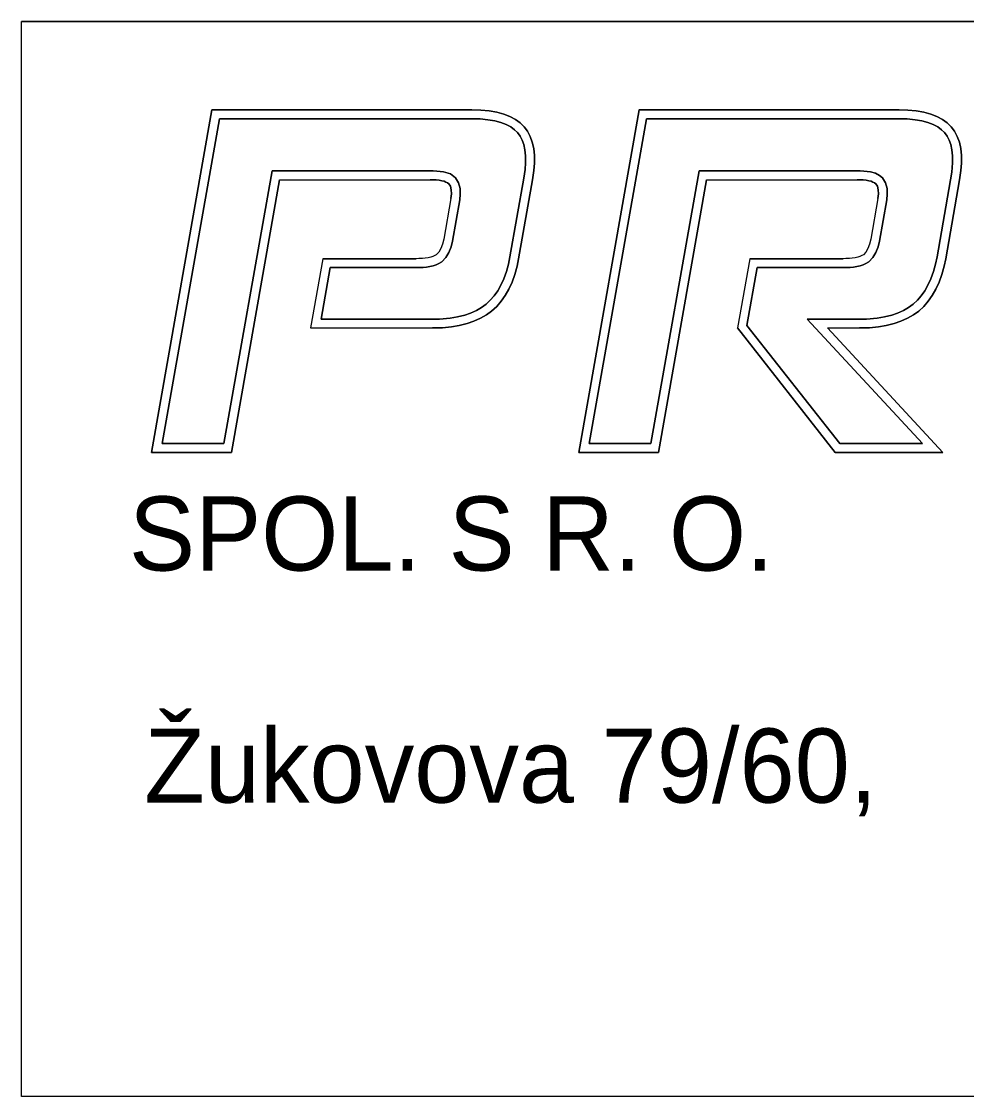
# Model space of a CAD drawing. Extents: x 362 to 677, y 239 to 384.
# Drawn here: x 645.31 to 657.42, y 260.9 to 274.68 of the extents above; entities that cross this region are included whole.
import ezdxf

# ---------------------------------------------------------------- set-up
doc = ezdxf.new("R2010")
doc.units = 0
doc.layers.add('000_rozpiska', color=7, linetype='Continuous')

msp = doc.modelspace()

# ---------------------------------------------------------------- linework, layer by layer
at = {"layer": '000_rozpiska'}
for p, q in [((672.386, 274.68), (645.311, 274.68)), ((645.311, 260.904), (645.311, 274.68)), ((646.979, 269.157), (647.752, 273.548)), ((647.751, 273.548), (651.083, 273.548)), ((652.45, 269.157), (653.223, 273.548)), ((653.222, 273.548), (656.554, 273.548)), ((648.617, 272.653), (648.001, 269.157)), ((648.617, 272.653), (650.546, 272.653)), ((651.86, 272.653), (651.681, 271.64)), ((654.088, 272.653), (653.472, 269.157)), ((654.088, 272.653), (656.017, 272.653)), ((657.331, 272.653), (657.152, 271.64)), ((650.812, 272.41), (650.721, 271.89)), ((656.283, 272.41), (656.192, 271.89)), ((649.171, 271.64), (649.014, 270.753)), ((649.171, 271.64), (650.367, 271.64)), ((654.642, 271.64), (654.485, 270.753)), ((654.642, 271.64), (655.838, 271.64)), ((649.014, 270.753), (650.579, 270.753)), ((655.738, 269.157), (654.485, 270.753)), ((655.639, 270.753), (656.05, 270.753)), ((657.114, 269.157), (655.639, 270.753)), ((648.001, 269.157), (646.979, 269.157)), ((653.472, 269.157), (652.45, 269.157)), ((657.114, 269.157), (655.738, 269.157)), ((673.621, 260.904), (645.311, 260.904))]:
    msp.add_line(p, q, dxfattribs=at)
for points in [[(645.311, 260.904), (645.311, 274.68), (672.386, 274.68)], [(651.49, 273.494), (651.401, 273.518), (651.303, 273.535), (651.196, 273.545), (651.083, 273.548), (647.752, 273.548), (646.979, 269.157), (648.001, 269.157), (648.617, 272.653), (650.546, 272.653), (650.581, 272.652), (650.622, 272.65), (650.662, 272.646), (650.695, 272.64), (650.725, 272.633), (650.749, 272.623), (650.77, 272.612), (650.786, 272.599), (650.806, 272.568), (650.818, 272.525), (650.819, 272.47), (650.812, 272.41), (650.721, 271.89), (650.706, 271.827), (650.684, 271.77), (650.658, 271.725), (650.626, 271.692), (650.606, 271.68), (650.583, 271.669), (650.554, 271.66), (650.522, 271.652), (650.485, 271.647), (650.447, 271.643), (650.402, 271.641), (650.367, 271.64), (649.171, 271.64), (649.014, 270.753), (650.579, 270.753), (650.706, 270.756), (650.819, 270.767), (650.92, 270.783), (651.022, 270.809), (651.107, 270.838), (651.193, 270.877), (651.267, 270.92), (651.335, 270.97), (651.4, 271.028), (651.457, 271.096), (651.509, 271.169), (651.556, 271.251), (651.597, 271.34), (651.632, 271.44), (651.661, 271.543), (651.681, 271.64), (651.86, 272.653), (651.877, 272.772), (651.884, 272.864), (651.882, 272.964), (651.874, 273.052), (651.856, 273.135), (651.83, 273.206), (651.796, 273.273), (651.752, 273.331), (651.7, 273.382), (651.639, 273.426), (651.568, 273.463), (651.49, 273.494)], [(651.083, 273.548), (651.196, 273.545), (651.303, 273.535), (651.401, 273.518), (651.49, 273.494), (651.568, 273.463), (651.639, 273.426), (651.7, 273.382), (651.752, 273.331), (651.796, 273.273), (651.83, 273.206), (651.856, 273.135), (651.874, 273.052), (651.882, 272.964), (651.884, 272.864), (651.877, 272.772), (651.86, 272.653)], [(657.348, 272.772), (657.355, 272.864), (657.353, 272.964), (657.345, 273.052), (657.327, 273.135), (657.301, 273.206), (657.267, 273.273), (657.223, 273.331), (657.171, 273.382), (657.11, 273.426), (657.039, 273.463), (656.961, 273.494), (656.872, 273.518), (656.774, 273.535), (656.667, 273.545), (656.554, 273.548), (653.223, 273.548), (652.45, 269.157), (653.472, 269.157), (654.088, 272.653), (656.017, 272.653), (656.052, 272.652), (656.093, 272.65), (656.133, 272.646), (656.166, 272.64), (656.196, 272.633), (656.22, 272.623), (656.241, 272.612), (656.257, 272.599), (656.277, 272.568), (656.288, 272.525), (656.29, 272.47), (656.283, 272.41), (656.192, 271.89), (656.177, 271.827), (656.155, 271.77), (656.129, 271.725), (656.097, 271.692), (656.077, 271.68), (656.054, 271.669), (656.025, 271.66), (655.993, 271.652), (655.956, 271.647), (655.918, 271.643), (655.873, 271.641), (655.838, 271.64), (654.642, 271.64), (654.485, 270.753), (655.738, 269.157), (657.114, 269.157), (655.639, 270.753), (656.05, 270.753), (656.177, 270.756), (656.29, 270.767), (656.391, 270.783), (656.493, 270.809), (656.578, 270.838), (656.664, 270.877), (656.738, 270.92), (656.806, 270.97), (656.871, 271.028), (656.928, 271.096), (656.98, 271.169), (657.027, 271.251), (657.068, 271.34), (657.103, 271.44), (657.132, 271.543), (657.152, 271.64), (657.331, 272.653), (657.348, 272.772)], [(656.554, 273.548), (656.667, 273.545), (656.774, 273.535), (656.872, 273.518), (656.961, 273.494), (657.039, 273.463), (657.11, 273.426), (657.171, 273.382), (657.223, 273.331), (657.267, 273.273), (657.301, 273.206), (657.327, 273.135), (657.345, 273.052), (657.353, 272.964), (657.355, 272.864), (657.348, 272.772), (657.331, 272.653)], [(673.621, 273.445), (673.621, 260.904), (645.311, 260.904)], [(647.848, 273.434), (651.08, 273.434), (651.189, 273.431), (651.288, 273.422), (651.377, 273.406), (651.454, 273.385), (651.52, 273.36), (651.579, 273.329), (651.626, 273.294), (651.666, 273.256), (651.699, 273.212), (651.725, 273.161), (651.746, 273.103), (651.761, 273.034), (651.768, 272.958), (651.77, 272.868), (651.764, 272.785), (651.747, 272.671), (651.57, 271.664), (651.55, 271.571), (651.524, 271.475), (651.491, 271.383), (651.454, 271.303), (651.413, 271.23), (651.367, 271.165), (651.318, 271.108), (651.263, 271.058), (651.205, 271.016), (651.14, 270.978), (651.065, 270.944), (650.99, 270.918), (650.897, 270.895), (650.804, 270.88), (650.666, 270.867), (649.15, 270.867), (649.266, 271.526), (650.369, 271.526), (650.406, 271.527), (650.456, 271.529), (650.499, 271.534), (650.543, 271.54), (650.584, 271.55), (650.625, 271.563), (650.66, 271.579), (650.697, 271.602), (650.75, 271.655), (650.788, 271.721), (650.815, 271.793), (650.832, 271.867), (650.926, 272.397), (650.933, 272.466), (650.931, 272.541), (650.912, 272.614), (650.872, 272.676), (650.807, 272.729), (650.719, 272.752), (650.677, 272.759), (650.632, 272.764), (650.585, 272.766), (650.549, 272.767), (648.521, 272.767), (647.905, 269.271), (647.115, 269.271), (647.848, 273.434)], [(651.761, 273.034), (651.746, 273.103), (651.725, 273.161), (651.699, 273.212), (651.666, 273.256), (651.626, 273.294), (651.579, 273.329), (651.52, 273.36), (651.454, 273.385), (651.377, 273.406), (651.288, 273.422), (651.189, 273.431), (651.08, 273.434), (647.848, 273.434), (647.115, 269.271), (647.905, 269.271), (648.521, 272.767), (650.549, 272.767), (650.585, 272.766), (650.632, 272.764), (650.677, 272.759), (650.719, 272.752), (650.807, 272.729), (650.872, 272.676), (650.912, 272.614), (650.931, 272.541), (650.933, 272.466), (650.926, 272.397), (650.832, 271.867), (650.815, 271.793), (650.788, 271.721), (650.75, 271.655), (650.697, 271.602), (650.66, 271.579), (650.625, 271.563), (650.584, 271.55), (650.543, 271.54), (650.499, 271.534), (650.456, 271.529), (650.406, 271.527), (650.369, 271.526), (649.266, 271.526), (649.15, 270.867), (650.666, 270.867), (650.804, 270.88), (650.897, 270.895), (650.99, 270.918), (651.065, 270.944), (651.14, 270.978), (651.205, 271.016), (651.263, 271.058), (651.318, 271.108), (651.367, 271.165), (651.413, 271.23), (651.454, 271.303), (651.491, 271.383), (651.524, 271.475), (651.55, 271.571), (651.57, 271.664), (651.747, 272.671), (651.764, 272.785), (651.77, 272.868), (651.768, 272.958), (651.761, 273.034)], [(648.521, 272.767), (647.905, 269.271), (647.115, 269.271), (647.848, 273.434), (651.08, 273.434), (651.189, 273.431), (651.288, 273.422), (651.377, 273.406), (651.454, 273.385), (651.52, 273.36), (651.579, 273.329), (651.626, 273.294), (651.666, 273.256), (651.699, 273.212), (651.725, 273.161), (651.746, 273.103), (651.761, 273.034), (651.768, 272.958), (651.77, 272.868), (651.764, 272.785), (651.747, 272.671), (651.57, 271.664), (651.55, 271.571), (651.524, 271.475), (651.491, 271.383), (651.454, 271.303), (651.413, 271.23), (651.367, 271.165), (651.318, 271.108), (651.263, 271.058), (651.205, 271.016), (651.14, 270.978), (651.065, 270.944), (650.99, 270.918), (650.897, 270.895), (650.804, 270.88), (650.666, 270.867), (649.15, 270.867), (649.266, 271.526), (650.369, 271.526), (650.406, 271.527), (650.456, 271.529), (650.499, 271.534), (650.543, 271.54), (650.584, 271.55), (650.625, 271.563), (650.66, 271.579), (650.697, 271.602), (650.75, 271.655), (650.788, 271.721), (650.815, 271.793), (650.832, 271.867), (650.926, 272.397), (650.933, 272.466), (650.931, 272.541), (650.912, 272.614), (650.872, 272.676), (650.807, 272.729), (650.719, 272.752), (650.677, 272.759), (650.632, 272.764), (650.585, 272.766), (650.549, 272.767), (648.521, 272.767)], [(653.992, 272.767), (653.376, 269.271), (652.586, 269.271), (653.319, 273.434), (656.551, 273.434), (656.66, 273.431), (656.759, 273.422), (656.848, 273.406), (656.925, 273.385), (656.991, 273.36), (657.05, 273.329), (657.097, 273.294), (657.137, 273.256), (657.17, 273.212), (657.196, 273.161), (657.217, 273.103), (657.232, 273.034), (657.239, 272.958), (657.241, 272.868), (657.232, 272.748), (657.041, 271.664), (657.021, 271.571), (656.995, 271.475), (656.962, 271.383), (656.925, 271.303), (656.884, 271.23), (656.838, 271.165), (656.789, 271.108), (656.734, 271.058), (656.676, 271.016), (656.611, 270.978), (656.536, 270.944), (656.461, 270.918), (656.368, 270.895), (656.275, 270.88), (656.137, 270.867), (655.378, 270.867), (656.853, 269.271), (655.794, 269.271), (654.606, 270.783), (654.737, 271.526), (655.84, 271.526), (655.877, 271.527), (655.927, 271.529), (655.97, 271.534), (656.014, 271.54), (656.055, 271.55), (656.096, 271.563), (656.131, 271.579), (656.168, 271.602), (656.22, 271.655), (656.259, 271.721), (656.286, 271.793), (656.303, 271.867), (656.397, 272.397), (656.404, 272.466), (656.402, 272.541), (656.383, 272.614), (656.343, 272.676), (656.305, 272.707), (656.252, 272.736), (656.19, 272.752), (656.148, 272.759), (656.102, 272.764), (656.056, 272.766), (656.019, 272.767), (653.992, 272.767)], [(657.196, 273.161), (657.17, 273.212), (657.137, 273.256), (657.097, 273.294), (657.05, 273.329), (656.991, 273.36), (656.925, 273.385), (656.848, 273.406), (656.759, 273.422), (656.66, 273.431), (656.551, 273.434), (653.319, 273.434), (652.586, 269.271), (653.376, 269.271), (653.992, 272.767), (656.019, 272.767), (656.056, 272.766), (656.102, 272.764), (656.148, 272.759), (656.19, 272.752), (656.252, 272.736), (656.305, 272.707), (656.343, 272.676), (656.383, 272.614), (656.402, 272.541), (656.404, 272.466), (656.397, 272.397), (656.303, 271.867), (656.286, 271.793), (656.259, 271.721), (656.22, 271.655), (656.168, 271.602), (656.131, 271.579), (656.096, 271.563), (656.055, 271.55), (656.014, 271.54), (655.97, 271.534), (655.927, 271.529), (655.877, 271.527), (655.84, 271.526), (654.737, 271.526), (654.606, 270.783), (655.794, 269.271), (656.853, 269.271), (655.378, 270.867), (656.137, 270.867), (656.275, 270.88), (656.368, 270.895), (656.461, 270.918), (656.536, 270.944), (656.611, 270.978), (656.676, 271.016), (656.734, 271.058), (656.789, 271.108), (656.838, 271.165), (656.884, 271.23), (656.925, 271.303), (656.962, 271.383), (656.995, 271.475), (657.021, 271.571), (657.041, 271.664), (657.232, 272.748), (657.241, 272.868), (657.239, 272.958), (657.232, 273.034), (657.217, 273.103), (657.196, 273.161)], [(653.992, 272.767), (653.376, 269.271), (652.586, 269.271), (653.319, 273.434), (656.551, 273.434), (656.66, 273.431), (656.759, 273.422), (656.848, 273.406), (656.925, 273.385), (656.991, 273.36), (657.05, 273.329), (657.097, 273.294), (657.137, 273.256), (657.17, 273.212), (657.196, 273.161), (657.217, 273.103), (657.232, 273.034), (657.239, 272.958), (657.241, 272.868), (657.232, 272.748), (657.041, 271.664), (657.021, 271.571), (656.995, 271.475), (656.962, 271.383), (656.925, 271.303), (656.884, 271.23), (656.838, 271.165), (656.789, 271.108), (656.734, 271.058), (656.676, 271.016), (656.611, 270.978), (656.536, 270.944), (656.461, 270.918), (656.368, 270.895), (656.275, 270.88), (656.137, 270.867), (655.378, 270.867), (656.853, 269.271), (655.794, 269.271), (654.606, 270.783), (654.737, 271.526), (655.84, 271.526), (655.877, 271.527), (655.927, 271.529), (655.97, 271.534), (656.014, 271.54), (656.055, 271.55), (656.096, 271.563), (656.131, 271.579), (656.168, 271.602), (656.22, 271.655), (656.259, 271.721), (656.286, 271.793), (656.303, 271.867), (656.397, 272.397), (656.404, 272.466), (656.402, 272.541), (656.383, 272.614), (656.343, 272.676), (656.305, 272.707), (656.252, 272.736), (656.19, 272.752), (656.148, 272.759), (656.102, 272.764), (656.056, 272.766), (656.019, 272.767), (653.992, 272.767)], [(650.725, 272.633), (650.695, 272.64), (650.662, 272.646), (650.622, 272.65), (650.581, 272.652), (650.546, 272.653)], [(650.812, 272.41), (650.819, 272.47), (650.818, 272.525), (650.806, 272.568), (650.786, 272.599), (650.77, 272.612), (650.749, 272.623), (650.725, 272.633)], [(656.196, 272.633), (656.166, 272.64), (656.133, 272.646), (656.093, 272.65), (656.052, 272.652), (656.017, 272.653)], [(656.283, 272.41), (656.29, 272.47), (656.288, 272.525), (656.277, 272.568), (656.257, 272.599), (656.241, 272.612), (656.22, 272.623), (656.196, 272.633)], [(650.721, 271.89), (650.706, 271.827), (650.684, 271.77), (650.658, 271.725), (650.626, 271.692), (650.606, 271.68), (650.583, 271.669), (650.554, 271.66), (650.522, 271.652), (650.485, 271.647), (650.447, 271.643), (650.402, 271.641), (650.367, 271.64)], [(656.192, 271.89), (656.177, 271.827), (656.155, 271.77), (656.129, 271.725), (656.097, 271.692), (656.077, 271.68), (656.054, 271.669), (656.025, 271.66), (655.993, 271.652), (655.956, 271.647), (655.918, 271.643), (655.873, 271.641), (655.838, 271.64)], [(651.681, 271.64), (651.661, 271.543), (651.632, 271.44), (651.597, 271.34), (651.556, 271.251), (651.509, 271.169), (651.457, 271.096), (651.4, 271.028), (651.335, 270.97), (651.267, 270.92), (651.193, 270.877), (651.107, 270.838), (651.022, 270.809), (650.92, 270.783), (650.819, 270.767), (650.706, 270.756), (650.579, 270.753)], [(657.152, 271.64), (657.132, 271.543), (657.103, 271.44), (657.068, 271.34), (657.027, 271.251), (656.98, 271.169), (656.928, 271.096), (656.871, 271.028), (656.806, 270.97), (656.738, 270.92), (656.664, 270.877), (656.578, 270.838), (656.493, 270.809), (656.391, 270.783), (656.29, 270.767), (656.177, 270.756), (656.05, 270.753)]]:
    msp.add_lwpolyline(points, dxfattribs=at)

# ---------------------------------------------------------------- texts
for s, p in [('SPOL. S R. O.', (646.688, 267.644)), ('Žukovova 79/60, ', (646.884, 264.67))]:
    msp.add_text(s, height=0.95, dxfattribs=at).set_placement(p)

doc.saveas('drawing.dxf')
